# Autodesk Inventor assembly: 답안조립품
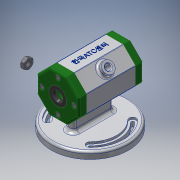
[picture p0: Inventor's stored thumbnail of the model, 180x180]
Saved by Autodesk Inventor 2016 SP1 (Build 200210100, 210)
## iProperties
Created: 2017-06
Part Number: 답안조립품
Material: 일반
Document SubType Name: Assembly
Designer: basic
Author: basic
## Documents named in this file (8)
- C:\Users\basic\Desktop\470608V1008\답안조립품.iam
- C:\Users\basic\Desktop\470608V1008\본체.ipt
- C:\Users\basic\Desktop\470608V1008\베어링 15 x 32 x 9.ipt
- C:\Users\basic\Desktop\470608V1008\뒤커버.ipt
- C:\Users\basic\Desktop\470608V1008\앞커버.ipt
- C:\Users\basic\Desktop\470608V1008\오일 실 15 25 7.ipt
- C:\Users\basic\Desktop\470608V1008\너트 M 8.ipt
- C:\Users\basic\Desktop\470608V1008\볼트 M4 x 12.ipt
